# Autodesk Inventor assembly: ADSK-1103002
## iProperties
Shininess: 50.0
Length Units: 11272
Angle Units: 11279
Time Units: 11290
Mass Units: 11286
Length Display Precision: 4
Angle Display Precision: 2
Compacted: True
Created: 2000-08
Part Number: ADSK-1103002
Document SubType Name: Assembly
Description: CLUTCH BEARING
Mass: 14.3665 g
Surface Area: 53.48 cm^2
Volume: 2.58778 cm^3
Density: 5.55167 g/cm^3
Designer: Autodesk, Inc.
Density: 0.0
Volumn: 0.0
Area: 0.0
PropertySet Name: Model Information
Control State: 0
Master: False
Checked Out: False
Title: samples
Author: Autodesk, Inc.
